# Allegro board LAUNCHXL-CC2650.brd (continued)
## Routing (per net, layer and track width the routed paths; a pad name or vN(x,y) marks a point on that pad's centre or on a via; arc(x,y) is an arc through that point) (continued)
N949215: length 3.8
  TOP w0.15: U5.70 15.7,80.4 R20.1 R21.1 R17.1
N949243: length 2.1
  TOP w0.15: U5.60 20.59,76.2 21.09,75.7 R30.1
N949263: length 2.9
  TOP w0.15: U7.5 15.53,84.15 R34.2 C47.2 17.38,83.98 R33.1
N949375: length 2.2
  TOP w0.15: U5.59 19.96,75.8 20.96,74.8 R28.2
N949517: length 2.3
  TOP w0.15: R24.1 R22.1 U5.1
N949687: length 6.3
  TOP w0.15: U5.89 8.1,80.25 8.18,80.33 8.18,82.72 7.3,83.6 Y3.3 7.3,83.9 7.9,84.5 7.9,84.9
  TOP w0.2: C34.1 7.9,84.9
N949695: length 4.1
  TOP w0.15: C33.1 9.8,82.5 9,81.7 Y3.1 8.5,81 U5.88
N950083: length 5.9
  TOP w0.15: U5.9 8.5,62.9 R18.1 C32.1 C50.1 9.91,61.6 10.5,61 U6.3
N950235: length 2.2
  TOP w0.15: U5.95 5.7,80.48 5.4,80.77 R67.2 5.4,81.4
N951001: length 2.2
  TOP w0.15: U5.63 19.96,77.4 20.96,78.4 R39.2
N951013: length 1.9
  TOP w0.15: U5.61 R29.1
N951017: length 2
  TOP w0.15: 19.2,77 20.46,77 20.96,77.5 R27.2
N952443: length 3.9
  TOP w0.15: 18.33,80.9 17.73,80.3 16.65,80.3 16.5,80.15 U5.68 ; 18.33,80.9 C46.1 ; 18.33,80.9 R31.1
N1004371: length 7
  TOP w0.15: U5.3 6.1,64.61 5.81,64.9 4.93,64.9 2.81,62.79 1.47,62.79 1,63.26 R23.2
N1004534: length 6.2
  TOP w0.15: R25.2 2.88,63.28 4.8,65.2 6.15,65.2 6.5,64.85 U5.4
N1013277: length 6.8
  TOP w0.15: U1.46 25.57,30.82 24.55,29.8 23.08,29.8 22.78,29.5 21.2,29.5 Y2.3
N1013851: length 2.7
  TOP w0.3: L21.1 27.6,27.38 C21.2 27.58,27.92 27.4,28.1 U1.2
N1013859: length 2.7
  TOP w0.3: C11.1 L11.1 26.7,27.95 26.9,28.15 U1.1
N1013883: length 0.9
  TOP w0.3: C31.1 L11.2 25.9,27.4
N1013899: length 3
  TOP w0.3: L21.2 27.6,25.1 C12.1 26.7,25.2 C11.2
  TOP w0.5: L12.1 C12.1
N1013927: length 1.7
  TOP w0.3: 27.2,22.08 C13.2 27.2,22.12
  TOP w0.5: L12.2 27.2,22.12 ; L13.1 27.2,22.08
N1013977: length 1.1
  TOP w0.5: C51.2 C15.1
N1014081: length 1.5
  TOP w0.3: U1.23 33.62,34.82 34.2,35.4 C19.1
N1014101: length 9.5
  TOP w0.15: U1.3 27.9,28.82 28.25,28.47 28.32,28.47 31.3,25.49 31.3,24.1 32.1,23.3 Y1.1 C17.1
N1014113: length 7.1
  TOP w0.15: U1.4 28.4,28.82 31.42,25.8 Y1.2 32.6,25.8 C18.1
N1014125: length 4
  TOP w0.5: C24.1 C51.1
N1014335: length 1
  TOP w0.5: L13.2 C24.2
N1018937: length 5.1
  TOP w0.15: Y2.1 22,28.3 23.2,29.5 24.7,29.5 25.53,30.32 U1.47
N1031635: length 1.8
  TOP w0.3: 9.5,89 9.5,88.21 10.11,87.6 CR6.1
  vias: v1(7.3,90.6) v1(7.7,89.3) v1(15.2,89.6) v1(15.6,90.5)
N1105722: length 1.2
  TOP w0.15: CR1.2 R15.1
N1105771: length 1.2
  TOP w0.15: CR2.2 R14.1
N1105824: length 2.9
  TOP w0.2: P6.1 16.61,16.73 16.64,16.7 R14.2 16.64,16.2
N1106228: length 2.9
  TOP w0.2: 19.14,16.2 R15.2 19.14,18.11 19.15,18.12 P6.3
N1176544: length 6.3
  TOP w0.15: J2.13 48.56,29.22 48.53,29.2 R46.1
N1176548: length 6.3
  TOP w0.15: R47.1 48.53,26.7 48.56,26.68 J2.15
N1176568: length 6.3
  TOP w0.15: R48.1 48.51,24.1 48.56,24.14 J2.17
N1177007: length 6.2
  TOP w0.15: R49.1 J2.19
N1288065: length 3.4
  TOP w0.15: SW2.3 54.7,46.9 55.5,46.1 R55.1
N1288098: length 1.3
  TOP w0.15: R56.1 5.07,48.72 SW1.4
N1384129: length 4.4
  TOP w0.15: SW3.3 20.01,91.6 18.71,90.3 R57.1
N1409884: length 1.8
  TOP w0.15: R59.1 38,22.1 38.2,22.3 U4.3
N1409917: length 0.7
  TOP w0.15: U4.7 R60.1
N1429173: length 3.1
  TOP w0.5: C58.1 P11.1
N1432281: length 1.6
  TOP w0.15: U5.96 C59.1 4.48,79.18 R66.2
N10367920: length 1
  TOP w0.15: R25.1 CR5.2
N10368080: length 1
  TOP w0.15: R23.1 CR4.2

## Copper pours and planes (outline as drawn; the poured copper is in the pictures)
GND on TOP (solid shape): 9.5,55.1 1,55.1 0.7,56.1 0.5,57.3 0.5,60.1 9.5,60.1
GND on BOTTOM (solid shape): 9.5,55.1 1,55.1 0.7,56.1 0.5,57.3 0.5,60.1 9.5,60.1
GND on TOP: 24.2,27.9 24.2,21.2 29.2,21.2 29.2,27.9
GND on TOP: 25.8,13.9 25.8,12 29.3,12 29.3,13.9
GND on TOP: 0.5,90.1 0.5,93.84 0.78,94.52 1.46,94.8 6.5,94.8 6.5,93.6 6.6,93.6 6.6,90.1
GND on TOP: 0.5,12 0.5,44.5 0.76,46 1.49,47.34 2.7,50.8 1.49,54.26 0.76,55.6 0.5,57.1 0.5,93.84 0.78,94.52 1.46,94.8 6.5,94.8 6.5,93.6 8.1,93.6 8.1,91.5 10,91.5 10,93.6 12.8,93.6 12.8,91.5 14.7,91.5 14.7,93.6 16.3,93.6 16.3,94.8 57.04,94.8 57.72,94.52 58,93.84 58,57.1 57.74,55.6 57.01,54.26 55.8,50.8 57.01,47.34 57.74,46 58,44.5 58,12 29.1,12 29.1,13.7 25.9,13.7 25.9,12 ; 41 cut-outs
GND on TOP, BOTTOM: 53.3,90.2 53.3,94.8 57.04,94.8 57.72,94.52 58,93.84 58,90.2
GND on BOTTOM: 0.5,90.3 0.5,93.84 0.78,94.52 1.46,94.8 5.1,94.8 5.1,90.3
GND on BOTTOM: 0.5,12.1 0.5,44.5 0.76,46 1.49,47.34 2.7,50.7 1.62,54.1 1.55,54.18 1.49,54.26 1.3,54.52 1.12,54.8 0.66,55.91 0.5,57.1 0.5,57.29 0.5,57.3 0.5,93.84 0.78,94.52 1.46,94.8 6.5,94.8 6.5,93.6 8.1,93.6 8.1,91.5 10,91.5 10,93.6 12.8,93.6 12.8,91.5 14.7,91.5 14.7,93.6 16.3,93.6 16.3,94.8 57.04,94.8 57.72,94.52 58,93.84 58,93.6 58,60.8 58,57.1 57.9,56.3 57.84,56 57.86,56 57.53,55.08 57.01,54.26 55.8,50.8 57.01,47.34 57.74,46 58,44.5 58,12.1
GND on L2: 0.5,12.1 0.5,44.5 0.76,46 1.49,47.34 2.7,50.8 1.49,54.26 0.97,55.09 0.64,56 0.66,56 0.6,56.3 0.5,57.3 0.5,93.84 0.78,94.52 1.46,94.8 6.5,94.8 6.5,93.6 8.1,93.6 8.1,91.5 10,91.5 10,93.6 12.8,93.6 12.8,91.5 14.7,91.5 14.7,93.6 16.3,93.6 16.3,94.8 57.04,94.8 57.72,94.52 58,93.84 58,93.6 58,57.3 58,57.1 57.9,56.3 57.84,56 57.86,56 57.53,55.08 57.01,54.26 55.8,50.8 57.01,47.34 57.74,46 58,44.5 58,12.1 ; 2 cut-outs
Net_205 on TOP (solid shape): 24.32,11.31 25.52,11.31 25.52,12.05 26.52,12.05 26.52,10.02 18.52,10.02 18.52,7.35 24.32,7.35 24.32,8.15 23.32,8.15 23.32,9.36 26.45,9.36 26.97,10.12 26.97,12.05 27.43,12.05 27.43,9.97 26.52,8.65 26.52,8.15 25.52,8.15 25.52,6.35 41.92,6.35 41.92,5.14 16.34,5.14 16.34,11.31 23.32,11.31 23.32,12.05 24.32,12.05
USB_VBUS on L3: 10.3,89.9 12.4,89.9 14.9,87.4 14.9,86.3 14.3,85.7 8.9,85.7 7.9,86.7 7.9,87.5
XDS_VCC on L3: outline of 135 points within 0.6,60.1 23.1,84.2
N1031635 on TOP: 6.8,88.9 6.8,93.6 8.1,93.6 8.1,91.5 10,91.5 10,93.6 12.8,93.6 12.8,91.7 14.5,91.7 14.5,91.1 14.7,91.1 14.7,91.7 14.7,93.6 16,93.6 16,88.9 ; 1 cut-out
N1031635 on BOTTOM, L2: 6.8,88.9 6.8,93.6 8.1,93.6 8.1,91.5 10,91.5 10,93.6 12.8,93.6 12.8,91.5 14.7,91.5 14.7,93.6 16,93.6 16,88.9

Small or netless copper shapes (teardrops, artwork), in the pictures only: 5 on TOP

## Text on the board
Ref Des/Silkscreen Bottom: J1 | 1 | 10 | 21 | 30 | J3 | J4 | 31 | 40 | 11 | 20 | J2 | DIO23 | DIO22 | DIO24 | DIO3 | DIO2 | DIO0 | DIO1 | DIO25 | DIO27 | DIO28 | DIO29 | DIO30 | DIO26 | DIO7 | DIO6 | DIO20 | DIO19 | DIO18 | BPRST | For evaluation only; not FCC approved for resale | NC | DIO9 | DIO8 | DIO12 | DIO11 | LPRST | DIO13 | DIO14 | DIO15 | DIO10 | DIO21 | DIO4 | DIO5 | TMS | TCK | DIO16 | DIO17 | www.ti.com/launchpad | >>LAUNCHXL-CC2650 | CC2650 LaunchPad
Ref Des/Silkscreen Top: J1 | 10 | 1 | 21 | 30 | J3 | J4 | 40 | 31 | 20 | 11 | J2 | DIO23 | DIO22 | DIO24 | DIO3 | DIO2 | DIO13 | BTN-1 | DIO26 | DIO25 | DIO27 | DIO28 | DIO29 | DIO30 | DIO0 | DIO1 | Red: | DIO6 | LEDs | Green: | DIO7 | CC-ANTENNA-DK | Mount for: | CC2650 In | XDS110 Out | BP | LP | DIO20 | DIO19 | DIO18 | BPRST | VSENSE | BTN-2 | DIO14 | XDS110 | Power | Extern | Pwr | NC | DIO12 | DIO11 | LPRST | DIO9 | DIO8 | DIO15 | DIO10 | DIO21 | DIO4 | DIO5 | DIO17 | DIO16 | TMS | TCK | RXD<< | TXD>> | RESET | Reset | TDI | TDO | SWO | Rev: 1.3
XSECTION_CHART: L1: TOP CONDUCTOR - COPPER 0.035 MM | *  DIELECTRIC - FR-4 0.175 MM | L2: L2 PLANE - COPPER 0.035 MM | *  DIELECTRIC - FR-4 1.11 MM | L3: L3 PLANE - COPPER 0.035 MM | L4: BOTTOM CONDUCTOR - COPPER 0.035 MM | DESIGN CROSS SECTION CHART | ___________________________ | TOTAL THICKNESS 1.6 MM
User.6: FIGURE | SIZE | 0.2 | 0.201 | 1.05 | 1.1 | 3.2 | 0.899 | 1.001 | 1.3x0.6 | DRILL CHART: TOP to BOTTOM | ALL UNITS ARE IN MILLIMETERS | PLATED | NON-PLATED | QTY | 386 | 25 | 75 | 1 | 2 | 6 | 3 | 4
